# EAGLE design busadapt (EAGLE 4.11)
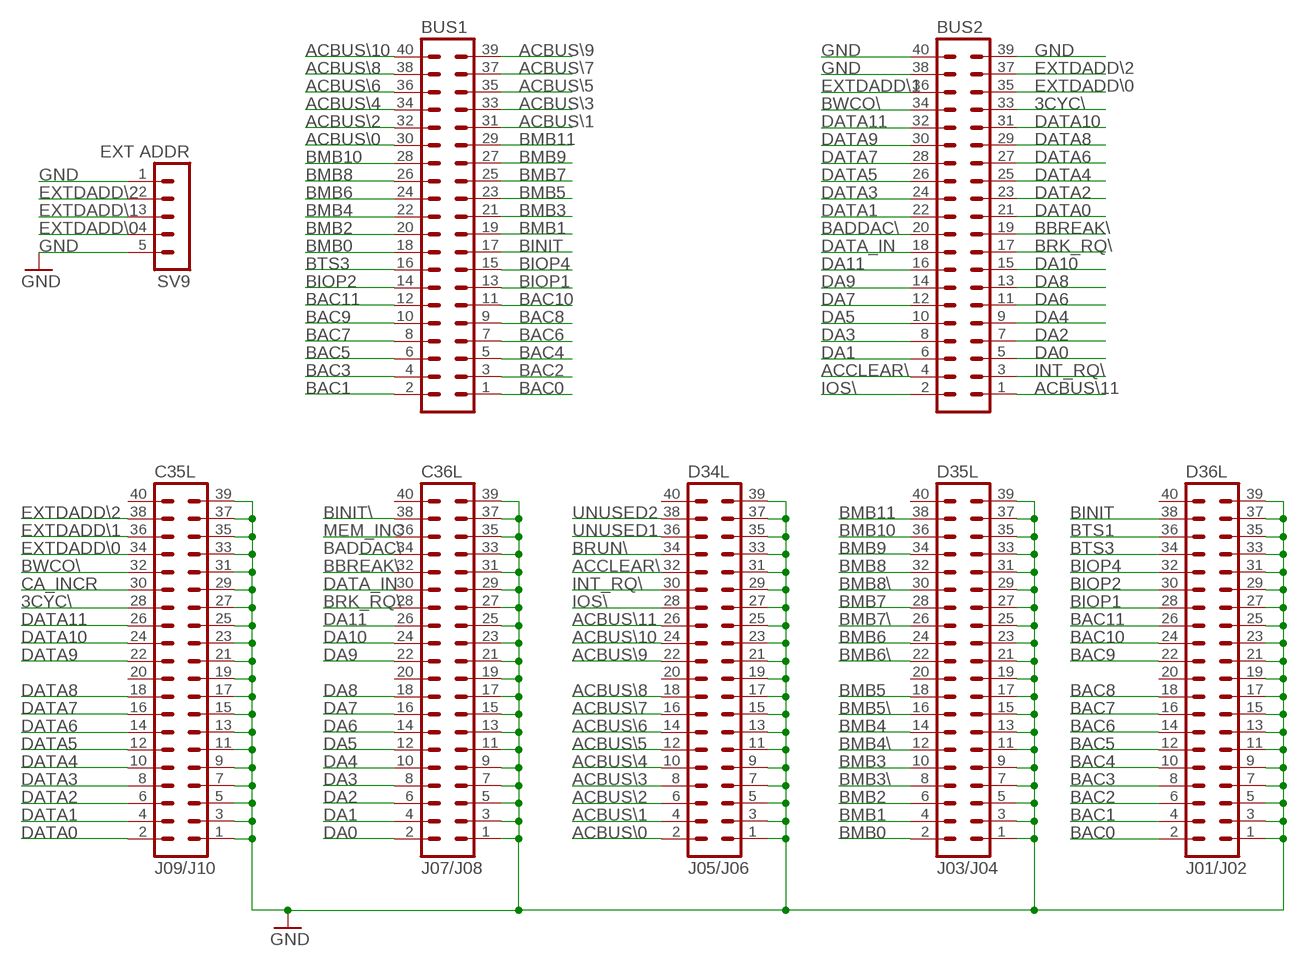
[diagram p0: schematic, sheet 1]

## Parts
BUS1  MA20-2  [MA20-2]
BUS2  MA20-2  [MA20-2]
C35L  J09/J10  MA20-2  [MA20-2]
C36L  J07/J08  MA20-2  [MA20-2]
D34L  J05/J06  MA20-2  [MA20-2]
D35L  J03/J04  MA20-2  [MA20-2]
D36L  J01/J02  MA20-2  [MA20-2]
SV9  EXT ADDR  MA05-1  [MA05-1]

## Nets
3CYC\: BUS2.33 C35L.28
ACBUS\0: BUS1.30 D34L.2
ACBUS\1: BUS1.31 D34L.4
ACBUS\2: BUS1.32 D34L.6
ACBUS\3: BUS1.33 D34L.8
ACBUS\4: BUS1.34 D34L.10
ACBUS\5: BUS1.35 D34L.12
ACBUS\6: BUS1.36 D34L.14
ACBUS\7: BUS1.37 D34L.16
ACBUS\8: BUS1.38 D34L.18
ACBUS\9: BUS1.39 D34L.22
ACBUS\10: BUS1.40 D34L.24
ACBUS\11: BUS2.1 D34L.26
ACCLEAR\: BUS2.4 D34L.32
BAC0: BUS1.1 D36L.2
BAC1: BUS1.2 D36L.4
BAC2: BUS1.3 D36L.6
BAC3: BUS1.4 D36L.8
BAC4: BUS1.5 D36L.10
BAC5: BUS1.6 D36L.12
BAC6: BUS1.7 D36L.14
BAC7: BUS1.8 D36L.16
BAC8: BUS1.9 D36L.18
BAC9: BUS1.10 D36L.22
BAC10: BUS1.11 D36L.24
BAC11: BUS1.12 D36L.26
BADDAC\: BUS2.20 C36L.34
BBREAK\: BUS2.19 C36L.32
BINIT: BUS1.17 D36L.38
BINIT\: C36L.38
BIOP1: BUS1.13 D36L.28
BIOP2: BUS1.14 D36L.30
BIOP4: BUS1.15 D36L.32
BMB0: BUS1.18 D35L.2
BMB1: BUS1.19 D35L.4
BMB2: BUS1.20 D35L.6
BMB3: BUS1.21 D35L.10
BMB3\: D35L.8
BMB4: BUS1.22 D35L.14
BMB4\: D35L.12
BMB5: BUS1.23 D35L.18
BMB5\: D35L.16
BMB6: BUS1.24 D35L.24
BMB6\: D35L.22
BMB7: BUS1.25 D35L.28
BMB7\: D35L.26
BMB8: BUS1.26 D35L.32
BMB8\: D35L.30
BMB9: BUS1.27 D35L.34
BMB10: BUS1.28 D35L.36
BMB11: BUS1.29 D35L.38
BRK_RQ\: BUS2.17 C36L.28
BRUN\: D34L.34
BTS1: D36L.36
BTS3: BUS1.16 D36L.34
BWCO\: BUS2.34 C35L.32
CA_INCR: C35L.30
DA0: BUS2.5 C36L.2
DA1: BUS2.6 C36L.4
DA2: BUS2.7 C36L.6
DA3: BUS2.8 C36L.8
DA4: BUS2.9 C36L.10
DA5: BUS2.10 C36L.12
DA6: BUS2.11 C36L.14
DA7: BUS2.12 C36L.16
DA8: BUS2.13 C36L.18
DA9: BUS2.14 C36L.22
DA10: BUS2.15 C36L.24
DA11: BUS2.16 C36L.26
DATA0: BUS2.21 C35L.2
DATA1: BUS2.22 C35L.4
DATA2: BUS2.23 C35L.6
DATA3: BUS2.24 C35L.8
DATA4: BUS2.25 C35L.10
DATA5: BUS2.26 C35L.12
DATA6: BUS2.27 C35L.14
DATA7: BUS2.28 C35L.16
DATA8: BUS2.29 C35L.18
DATA9: BUS2.30 C35L.22
DATA10: BUS2.31 C35L.24
DATA11: BUS2.32 C35L.26
DATA_IN: BUS2.18 C36L.30
EXTDADD\0: BUS2.35 C35L.34 SV9.4
EXTDADD\1: BUS2.36 C35L.36 SV9.3
EXTDADD\2: BUS2.37 C35L.38 SV9.2
GND: BUS2.38 BUS2.39 BUS2.40 C35L.1 C35L.3 C35L.5 C35L.7 C35L.9 C35L.11 C35L.13 C35L.15 C35L.17 C35L.19 C35L.21 C35L.23 C35L.25 C35L.27 C35L.29 C35L.31 C35L.33 C35L.35 C35L.37 C35L.39 C36L.1 C36L.3 C36L.5 C36L.7 C36L.9 C36L.11 C36L.13 C36L.15 C36L.17 C36L.19 C36L.21 C36L.23 C36L.25 C36L.27 C36L.29 C36L.31 C36L.33 C36L.35 C36L.37 C36L.39 D34L.1 D34L.3 D34L.5 D34L.7 D34L.9 D34L.11 D34L.13 D34L.15 D34L.17 D34L.19 D34L.21 D34L.23 D34L.25 D34L.27 D34L.29 D34L.31 D34L.33 D34L.35 D34L.37 D34L.39 D35L.1 D35L.3 D35L.5 D35L.7 D35L.9 D35L.11 D35L.13 D35L.15 D35L.17 D35L.19 D35L.21 D35L.23 D35L.25 D35L.27 D35L.29 D35L.31 D35L.33 D35L.35 D35L.37 D35L.39 D36L.1 D36L.3 D36L.5 D36L.7 D36L.9 D36L.11 D36L.13 D36L.15 D36L.17 D36L.19 D36L.21 D36L.23 D36L.25 D36L.27 D36L.29 D36L.31 D36L.33 D36L.35 D36L.37 D36L.39 SV9.1 SV9.5
INT_RQ\: BUS2.3 D34L.30
IOS\: BUS2.2 D34L.28
MEM_INC: C36L.36
UNUSED1: D34L.36
UNUSED2: D34L.38
Unconnected: C35L.20 C35L.40 C36L.20 C36L.40 D34L.20 D34L.40 D35L.20 D35L.40 D36L.20 D36L.40

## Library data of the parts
BUS1 BUS2 C35L C36L D34L D35L D36L = con-lstb:MA20-2: PIN HEADER
SV9 = con-lstb:MA05-1: PIN HEADER

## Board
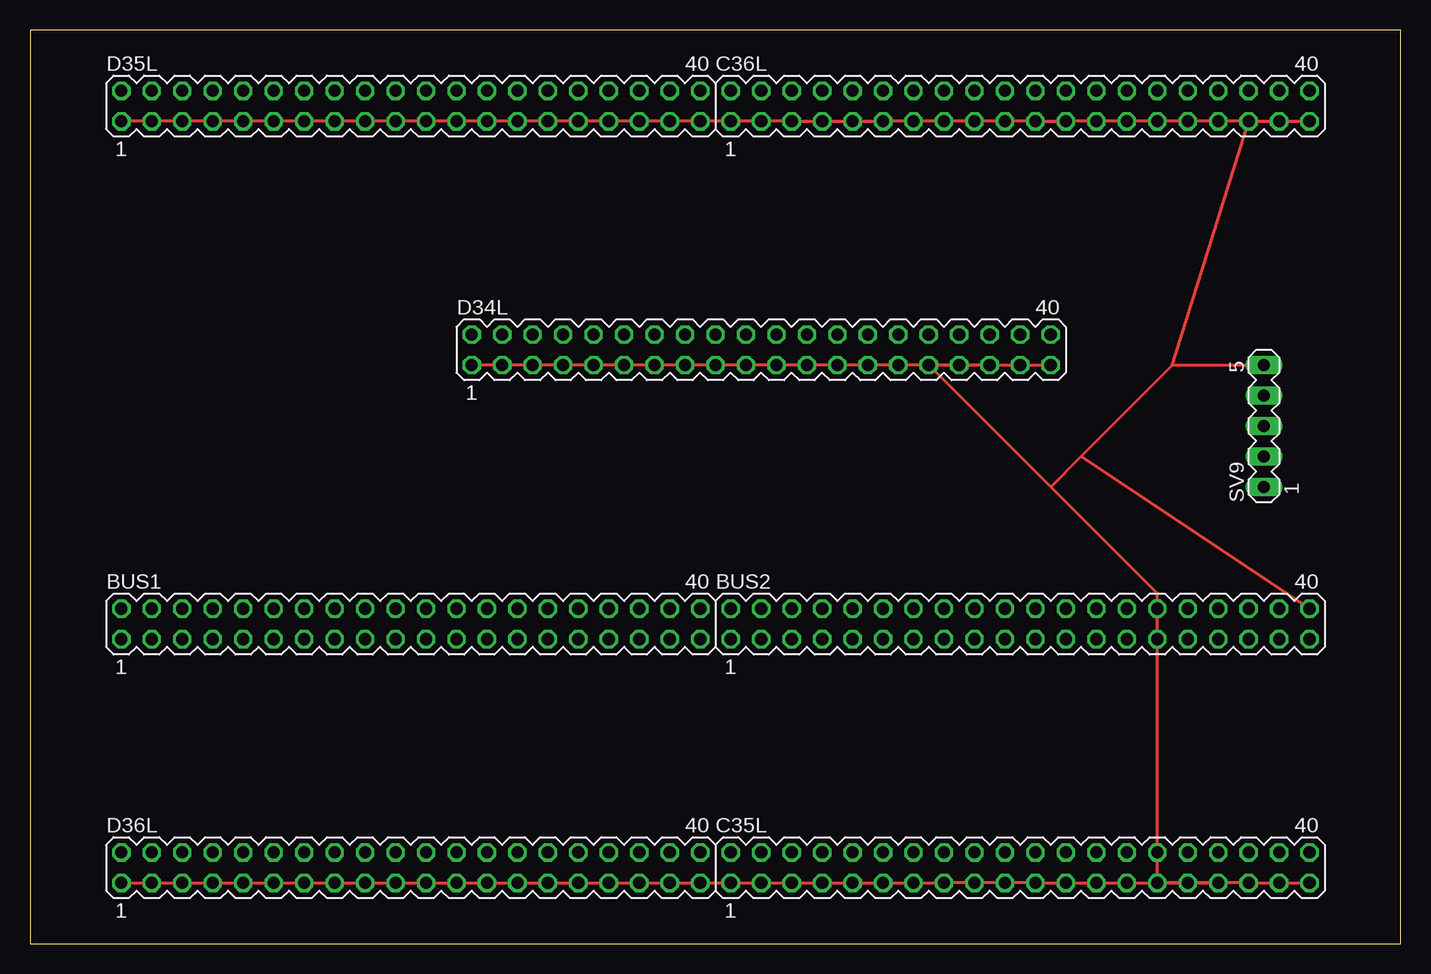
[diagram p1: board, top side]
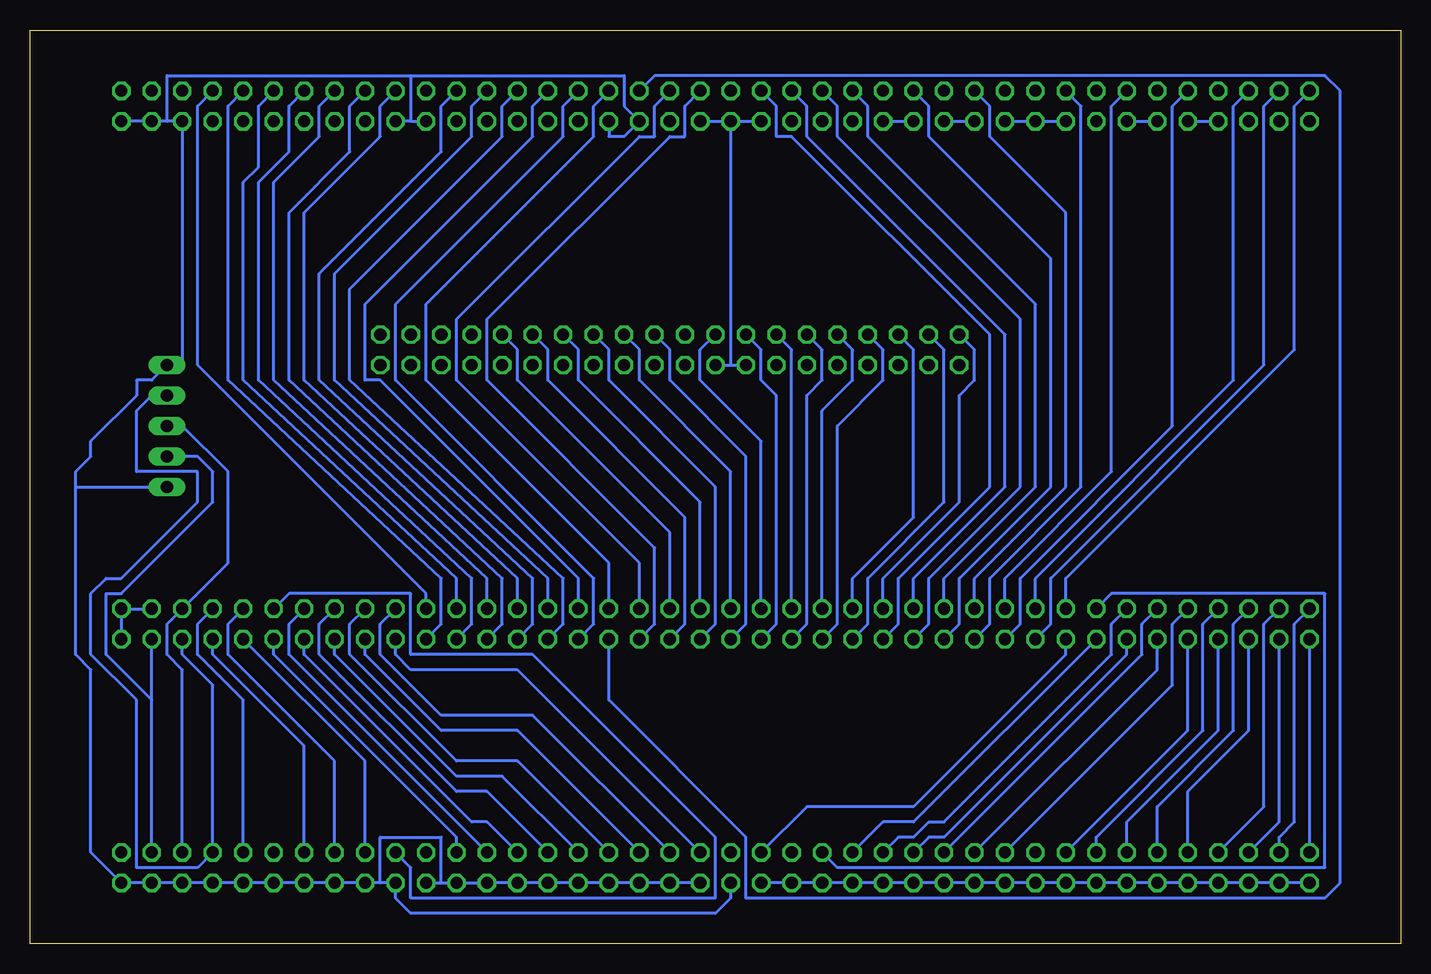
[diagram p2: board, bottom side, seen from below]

Size 114.29 x 76.19 mm. Coordinates in mm from the lower left corner, seen from the top.
Outline: 0,0 114.29,0 114.29,76.19 0,76.19 0,0
Copper layers (1*16): Top 0.035mm / dielectric 1.5mm / Bottom 0.035mm
Design rules "default": minimum track width 10mil, minimum drill 24mil, track to track 8mil, track to pad 8mil, pad to pad 8mil, via to via 8mil, smd to smd 8mil, copper to edge 40mil, drill to drill 8mil, minimum pad ring 10mil, minimum via ring 8mil, stop-mask expansion 4mil, vias tented up to drill 0mil, thermal gap 10mil

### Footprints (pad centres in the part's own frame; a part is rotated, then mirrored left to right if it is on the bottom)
MA20-2 = drill 1.016 octagon: 1 -24.13,-1.27; 2 -24.13,1.27; 3 -21.59,-1.27; 4 -21.59,1.27; 5 -19.05,-1.27; 6 -19.05,1.27; 7 -16.51,-1.27; 8 -16.51,1.27; 9 -13.97,-1.27; 10 -13.97,1.27; 11 -11.43,-1.27; 12 -11.43,1.27; 13 -8.89,-1.27; 14 -8.89,1.27; 15 -6.35,-1.27; 16 -6.35,1.27; 17 -3.81,-1.27; 18 -3.81,1.27; 19 -1.27,-1.27; 20 -1.27,1.27; 21 1.27,-1.27; 22 1.27,1.27; 23 3.81,-1.27; 24 3.81,1.27; 25 6.35,-1.27; 26 6.35,1.27; 27 8.89,-1.27; 28 8.89,1.27; 29 11.43,-1.27; 30 11.43,1.27; 31 13.97,-1.27; 32 13.97,1.27; 33 16.51,-1.27; 34 16.51,1.27; 35 19.05,-1.27; 36 19.05,1.27; 37 21.59,-1.27; 38 21.59,1.27; 39 24.13,-1.27; 40 24.13,1.27
MA05-1 = drill 1.016 long: 1 -5.08,0; 2 -2.54,0; 3 0,0; 4 2.54,0; 5 5.08,0

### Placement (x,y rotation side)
BUS1  31.74,26.67 0 top
BUS2  82.54,26.67 0 top
C35L  82.54,6.34 0 top
C36L  82.54,69.84 0 top
D34L  60.95,49.52 0 top
D35L  31.74,69.84 0 top
D36L  31.74,6.34 0 top
SV9  102.86,43.17 90 top

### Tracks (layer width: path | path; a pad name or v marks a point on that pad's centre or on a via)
3CYC\
  Bottom 0.254: C35L.28 91.43,16.51 99.05,24.12 BUS2.33
ACBUS\0
  Bottom 0.254: BUS1.30 43.17,30.48 36.82,36.82 36.82,45.71 35.55,46.98 35.55,49.52 D34L.2
ACBUS\1
  Bottom 0.254: BUS1.31 44.44,26.67 44.44,30.48 38.09,36.82 38.09,49.52 D34L.4
ACBUS\2
  Bottom 0.254: BUS1.32 45.71,30.48 40.63,35.55 40.63,49.52 D34L.6
ACBUS\3
  Bottom 0.254: BUS1.33 46.98,26.67 46.98,43.17 43.17,46.98 43.17,49.52 D34L.8
ACBUS\4
  Bottom 0.254: BUS1.34 48.25,44.45 45.71,46.98 45.71,49.52 D34L.10
ACBUS\5
  Bottom 0.254: BUS1.35 49.52,26.67 49.52,45.71 48.25,46.98 48.25,49.52 D34L.12
ACBUS\6
  Bottom 0.254: BUS1.36 50.79,49.52 D34L.14
ACBUS\7
  Bottom 0.254: BUS1.37 52.06,26.67 52.06,45.71 53.33,46.98 53.33,49.52 D34L.16
ACBUS\8
  Bottom 0.254: BUS1.38 53.33,41.9 58.41,46.98 58.41,49.52 D34L.18
ACBUS\9
  Bottom 0.254: BUS1.39 54.6,26.67 54.6,40.63 60.95,46.98 60.95,49.52 D34L.22
ACBUS\10
  Bottom 0.254: BUS1.40 55.87,39.36 63.49,46.98 63.49,49.52 D34L.24
ACBUS\11
  Bottom 0.254: BUS2.1 57.14,26.67 57.14,38.09 66.03,46.98 66.03,49.52 D34L.26
ACCLEAR\
  Bottom 0.254: BUS2.4 60.95,34.28 73.65,46.98 73.65,49.52 D34L.32
BAC0
  Bottom 0.254: D36L.2 BUS1.1
BAC1
  Bottom 0.254: D36L.4 10.15,8.88 8.88,10.15 8.88,26.67 BUS1.2
BAC2
  Bottom 0.254: D36L.6 10.15,10.15 BUS1.3
BAC3
  Bottom 0.254: BUS1.4 11.42,26.67 11.42,11.42 D36L.8
BAC4
  Bottom 0.254: D36L.10 17.77,12.69 12.69,17.78 BUS1.5
BAC5
  Bottom 0.254: D36L.12 20.31,11.42 13.96,17.78 13.96,26.67 BUS1.6
BAC6
  Bottom 0.254: BUS1.7 15.23,17.78 22.85,10.15 D36L.14
BAC7
  Bottom 0.254: BUS1.8 16.5,26.67 16.5,17.78 25.39,8.88 D36L.16
BAC8
  Bottom 0.254: BUS1.9 17.77,17.78 D36L.18
BAC9
  Bottom 0.254: D36L.22 19.04,21.59 19.04,26.67 BUS1.10
BAC10
  Bottom 0.254: D36L.24 20.31,22.86 BUS1.11
BAC11
  Bottom 0.254: D36L.26 21.58,24.12 21.58,26.67 BUS1.12
BADDAC\
  Bottom 0.254: C36L.34 100.32,69.84 100.32,48.25 81.27,29.21 BUS2.20
BBREAK\
  Bottom 0.254: BUS2.19 80,26.67 80,30.48 97.78,46.98 97.78,69.84 C36L.32
BINIT
  Bottom 0.254: BUS1.17 27.93,24.12 40.63,11.42 49.52,11.42 D36L.38
BIOP1
  Bottom 0.254: D36L.28 39.36,8.88 38.09,8.88 22.85,24.12 BUS1.13
BIOP2
  Bottom 0.254: BUS1.14 24.12,26.67 24.12,24.12 38.09,10.15 39.36,10.15 40.63,8.88 41.9,8.88 D36L.30
BIOP4
  Bottom 0.254: BUS1.15 40.63,10.15 43.17,10.15 D36L.32
BMB0
  Bottom 0.254: BUS1.18 27.93,30.48 8.88,49.52 8.88,69.84 D35L.2
BMB1
  Bottom 0.254: BUS1.19 29.2,26.67 29.2,30.48 11.42,48.25 11.42,69.84 D35L.4
BMB2
  Bottom 0.254: BUS1.20 30.47,30.48 13.96,46.98 13.96,69.84 D35L.6
BMB3
  Bottom 0.254: BUS1.21 31.74,26.67 31.74,30.48 19.04,43.17 19.04,69.84 D35L.10
BMB4
  Bottom 0.254: BUS1.22 33.01,30.48 24.12,39.36 24.12,69.84 D35L.14
BMB5
  Bottom 0.254: BUS1.23 34.28,26.67 34.28,30.48 26.66,38.09 26.66,69.84 D35L.18
BMB6
  Bottom 0.254: BUS1.24 35.55,30.48 27.93,38.09 27.93,60.95 34.28,67.31 34.28,69.84 D35L.24
BMB7
  Bottom 0.254: BUS1.25 36.82,26.67 36.82,30.48 29.2,38.09 29.2,57.14 39.36,67.31 39.36,69.84 D35L.28
BMB8
  Bottom 0.254: BUS1.26 38.09,30.48 30.47,38.09 30.47,53.34 44.44,67.31 44.44,69.84 D35L.32
BMB9
  Bottom 0.254: BUS1.27 39.36,26.67 39.36,30.48 31.74,38.09 31.74,52.06 46.98,67.31 46.98,69.84 D35L.34
BMB10
  Bottom 0.254: BUS1.28 40.63,30.48 33.01,38.09 33.01,50.79 49.52,67.31 49.52,69.84 D35L.36
BMB11
  Bottom 0.254: BUS1.29 41.9,26.67 41.9,30.48 34.28,38.09 34.28,50.79 50.79,67.31 52.06,67.31 52.06,69.84 D35L.38
BRK_RQ\
  Bottom 0.254: BUS2.17 77.46,26.67 77.46,30.48 95.24,46.98 95.24,63.49 92.7,66.04 92.7,69.84 C36L.28
BTS3
  Bottom 0.254: BUS1.16 24.12,29.21 6.34,29.21 6.34,6.34 46.98,6.34 D36L.34
BWCO\
  Bottom 0.254: C35L.32 96.51,20.32 100.32,24.12 100.32,26.67 BUS2.34
DA0
  Bottom 0.254: BUS2.5 62.22,26.67 62.22,33.02 76.19,46.98 76.19,52.06 60.95,67.31 59.68,67.31 59.68,69.84 C36L.2
DA1
  Bottom 0.254: BUS2.6 63.49,31.75 78.73,46.98 78.73,52.06 63.49,67.31 62.22,67.31 62.22,69.84 C36L.4
DA2
  Bottom 0.254: BUS2.7 66.03,20.32 54.6,8.88 54.6,3.81 6.34,3.81 5.07,5.08 5.07,71.12 6.34,72.39 62.22,72.39 C36L.6
DA3
  Bottom 0.254: BUS2.8 66.03,31.75 81.27,46.98 81.27,53.34 67.3,67.31 67.3,69.84 C36L.8
DA4
  Bottom 0.254: BUS2.9 67.3,26.67 67.3,30.48 83.81,46.98 83.81,53.34 69.84,67.31 69.84,69.84 C36L.10
DA5
  Bottom 0.254: C36L.12 72.38,69.84 72.38,67.31 86.35,53.34 86.35,46.98 85.08,46.98 68.57,30.48 BUS2.10
DA6
  Bottom 0.254: BUS2.11 69.84,26.67 69.84,30.48 87.62,46.98 87.62,54.6 74.92,67.31 74.92,69.84 C36L.14
DA7
  Bottom 0.254: BUS2.12 71.11,30.48 88.89,46.98 88.89,55.88 77.46,67.31 77.46,69.84 C36L.16
DA8
  Bottom 0.254: BUS2.13 72.38,26.67 72.38,30.48 90.16,46.98 90.16,55.88 80,66.04 80,69.84 C36L.18
DA9
  Bottom 0.254: BUS2.14 73.65,30.48 91.43,46.98 91.43,60.95 85.08,67.31 85.08,69.84 C36L.22
DA10
  Bottom 0.254: BUS2.15 74.92,26.67 74.92,30.48 92.7,46.98 92.7,60.95 87.62,66.04 87.62,69.84 C36L.24
DA11
  Bottom 0.254: BUS2.16 76.19,30.48 93.97,46.98 93.97,63.49 90.16,67.31 90.16,69.84 C36L.26
DATA0
  Bottom 0.254: C35L.2 73.65,22.86 82.54,22.86 83.81,24.12 BUS2.21
DATA1
  Bottom 0.254: C35L.4 72.38,19.05 80,19.05 85.08,24.12 85.08,26.67 BUS2.22
DATA2
  Bottom 0.254: C35L.6 73.65,17.78 80,17.78 86.35,24.12 BUS2.23
DATA3
  Bottom 0.254: C35L.8 73.65,15.23 78.73,15.23 87.62,24.12 87.62,26.67 BUS2.24
DATA4
  Bottom 0.254: C35L.10 74.92,13.96 78.73,13.96 88.89,24.12 BUS2.25
DATA5
  Bottom 0.254: C35L.12 76.19,12.69 78.73,12.69 90.16,24.12 90.16,26.67 BUS2.26
DATA6
  Bottom 0.254: C35L.14 76.19,10.15 77.46,10.15 91.43,24.12 BUS2.27
DATA7
  Bottom 0.254: C35L.16 92.7,24.12 92.7,26.67 BUS2.28
DATA8
  Bottom 0.254: C35L.18 78.73,8.88 93.97,24.12 BUS2.29
DATA9
  Bottom 0.254: C35L.22 82.54,6.34 82.54,3.81 57.14,3.81 57.14,8.88 72.38,24.12 82.54,24.12 82.54,29.21 92.7,29.21 BUS2.30
DATA10
  Bottom 0.254: C35L.24 86.35,15.23 BUS2.31
DATA11
  Bottom 0.254: C35L.26 88.89,15.23 97.78,24.12 97.78,26.67 BUS2.32
DATA_IN
  Bottom 0.254: BUS2.18 78.73,30.48 96.51,46.98 96.51,63.49 95.24,64.77 95.24,69.84 C36L.30
EXTDADD\0
  Bottom 0.254: BUS2.35 101.59,24.12 99.05,21.59 C35L.34 100.32,6.34 105.4,6.34 105.4,20.32 109.21,24.12 109.21,29.21 107.94,30.48 106.67,30.48 100.32,36.82 100.32,39.36 105.4,39.36 105.4,44.45 104.13,45.71 SV9.4
EXTDADD\1
  Bottom 0.254: 104.13,43.17 SV9.3 101.59,43.17 97.78,39.36 97.78,31.75 BUS2.36 102.86,26.67 102.86,24.12 101.59,22.86 C35L.36
EXTDADD\2
  Bottom 0.254: 104.13,20.32 BUS2.37 | C35L.38 104.13,20.32 | 104.13,20.32 107.94,24.12 107.94,29.21 106.67,29.21 99.05,36.82 99.05,39.36 100.32,40.63 SV9.2
GND
  Top 0.254: D36L.1 D36L.3 D36L.5 D36L.7 D36L.9 D36L.11 D36L.13 D36L.15 D36L.17 D36L.19 D36L.21 D36L.23 D36L.25 D36L.27 D36L.29 D36L.31 D36L.33 D36L.35 D36L.37 D36L.39 C35L.1 C35L.3 C35L.5 C35L.7 C35L.9 C35L.11 C35L.13 C35L.15 C35L.17 C35L.19 C35L.21 C35L.23 C35L.25 C35L.27 C35L.29 | C35L.29 C35L.31 C35L.33 C35L.29 | C35L.29 C35L.35 C35L.37 C35L.39 | D34L.1 D34L.3 D34L.5 D34L.7 D34L.9 D34L.11 D34L.13 D34L.15 D34L.17 D34L.19 D34L.21 D34L.23 D34L.25 D34L.27 D34L.29 D34L.31 | D34L.31 D34L.33 D34L.35 D34L.31 | D34L.31 D34L.37 D34L.39 | 85.08,38.09 D34L.31 | 85.08,38.09 93.97,29.21 C35L.29 | 85.08,38.09 87.62,40.63 | 87.62,40.63 95.24,48.25 | 87.62,40.63 BUS2.40 | D35L.1 D35L.3 D35L.5 D35L.7 D35L.9 D35L.11 D35L.13 D35L.15 D35L.17 D35L.19 D35L.21 D35L.23 D35L.25 D35L.27 D35L.29 D35L.31 D35L.33 D35L.35 D35L.37 D35L.39 C36L.1 C36L.3 C36L.5 C36L.7 C36L.9 C36L.11 C36L.13 C36L.15 C36L.17 C36L.19 C36L.21 C36L.23 C36L.25 C36L.27 C36L.29 C36L.31 C36L.33 C36L.35 | C36L.35 C36L.37 C36L.39 | 95.24,48.25 C36L.35 | 95.24,48.25 SV9.5
  Bottom 0.254: D36L.37 D36L.35 D36L.33 D36L.31 D36L.29 D36L.27 D36L.25 D36L.23 D36L.21 D36L.19 D36L.17 D36L.15 D36L.13 D36L.11 D36L.9 D36L.7 D36L.5 D36L.3 D36L.1 | D35L.9 D35L.7 | C35L.1 C35L.3 C35L.5 C35L.7 C35L.9 C35L.11 C35L.13 C35L.15 C35L.17 80,5.08 | C35L.19 80,5.08 | D36L.39 55.87,3.81 57.14,2.54 82.54,2.54 83.81,3.81 C35L.21 85.08,5.08 | 85.08,5.08 C35L.23 C35L.25 C35L.27 C35L.29 C35L.31 C35L.33 C35L.35 C35L.37 C35L.39 109.21,7.62 109.21,22.86 110.48,24.12 110.48,38.09 | 80,5.08 80,8.88 85.08,8.88 85.08,5.08 | C36L.7 66.03,67.31 64.76,67.31 C36L.5 64.76,69.84 64.76,72.39 82.54,72.39 | 82.54,68.58 C36L.21 | 82.54,68.58 C36L.19 | 82.54,72.39 82.54,68.58 | 102.86,68.58 C36L.37 C36L.39 | 102.86,68.58 C36L.35 101.59,48.25 SV9.5 104.13,46.98 105.4,46.98 105.4,45.71 109.21,41.9 109.21,40.63 110.48,39.36 110.48,38.09 | 82.54,72.39 102.86,72.39 102.86,68.58 | D35L.13 D35L.11 | D35L.17 D35L.19 D35L.21 | D35L.25 D35L.23 | D34L.17 55.87,48.25 | 55.87,48.25 D34L.15 | D35L.39 D35L.37 | C36L.1 D35L.39 | D35L.39 55.87,48.25 | D35L.29 D35L.27 | BUS2.39 BUS2.40 BUS2.38 | 110.48,38.09 SV9.1
INT_RQ\
  Bottom 0.254: BUS2.3 59.68,26.67 59.68,35.55 71.11,46.98 71.11,49.52 D34L.30
IOS\
  Bottom 0.254: BUS2.2 58.41,36.82 68.57,46.98 68.57,49.52 D34L.28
